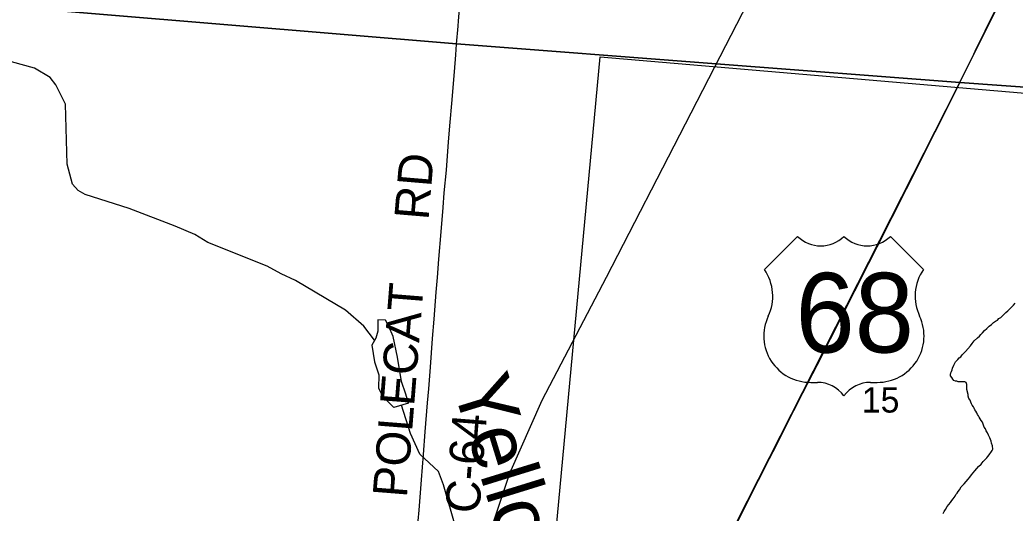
# Model space of a CAD drawing. Extents: x -1.4 to 35.4, y 0 to 22.
# Drawn here: x 19.136 to 20.785, y 18.063 to 18.879 of the extents above; entities that cross this region are included whole.
import ezdxf

# ---------------------------------------------------------------- set-up
doc = ezdxf.new("R2010")
doc.units = 0
for name, color, linetype in [('GM_X_County_Road', 7, 'Continuous'), ('GM_X_County_Road_Text', 7, 'Continuous'), ('GM_X_Minor_Lake', 7, 'Continuous'), ('GM_X_Minor_River', 7, 'Continuous'), ('GM_X_Minor_River_Text', 7, 'Continuous'), ('GM_X_Rail_Line', 7, 'Continuous'), ('GM_X_Section', 7, 'Continuous'), ('GM_X_Section_Text', 7, 'Continuous'), ('GM_X_US_Location', 7, 'Continuous'), ('GM_X_US_Route', 7, 'Continuous'), ('GM_X_US_Shield', 7, 'Continuous'), ('SC_Scratch1', 7, 'Continuous'), ('SH_Cut_Line', 7, 'Continuous')]:
    doc.layers.add(name, color=color, linetype=linetype)

msp = doc.modelspace()

# ---------------------------------------------------------------- linework, layer by layer
at = {"layer": 'GM_X_County_Road'}
for points in [[(19.8597, 18.8392), (19.8621, 18.8687), (19.8628, 18.878), (19.8637, 18.8904), (19.8646, 18.9027), (19.8649, 18.9089), (19.8663, 18.9274), (19.8686, 18.9584), (19.8715, 18.9955), (19.8746, 19.0326), (19.877, 19.0604), (19.8793, 19.0914), (19.8809, 19.1131), (19.8825, 19.1379), (19.884, 19.1782), (19.8852, 19.2247), (19.8856, 19.233)], [(19.8078, 18.1973), (19.8115, 18.2453), (19.8135, 18.2688), (19.8162, 18.3047), (19.8199, 18.3518), (19.8225, 18.384), (19.826, 18.4286), (19.8278, 18.4527), (19.8302, 18.483), (19.8339, 18.5282), (19.8372, 18.569), (19.8393, 18.5932), (19.8427, 18.6303), (19.8463, 18.6773), (19.849, 18.7102), (19.8517, 18.7411), (19.8562, 18.7931), (19.8586, 18.8216), (19.8597, 18.8392)], [(19.7944, 18.0245), (19.7945, 18.0255), (19.7962, 18.0502), (19.7974, 18.0675), (19.8013, 18.1177), (19.805, 18.1598), (19.8078, 18.1973)]]:
    msp.add_lwpolyline(points, dxfattribs=at)
at = {"layer": 'GM_X_Minor_Lake'}
for points in [[(19.78, 18.2446), (19.7757, 18.2598), (19.7686, 18.2809), (19.7618, 18.3209), (19.7545, 18.3552), (19.7473, 18.3716), (19.7418, 18.3824), (19.729, 18.383), (19.7293, 18.364), (19.7261, 18.3527), (19.719, 18.3411), (19.7238, 18.3133), (19.7306, 18.2919), (19.7305, 18.2699), (19.7374, 18.2561), (19.7556, 18.2379)], [(19.78, 18.2446), (19.7556, 18.2379)]]:
    msp.add_lwpolyline(points, dxfattribs=at)
at = {"layer": 'GM_X_Minor_River'}
for points in [[(19.7239, 18.349), (19.706, 18.3725), (19.6755, 18.3989), (19.5929, 18.4481), (19.5689, 18.4592), (19.546, 18.4714), (19.4476, 18.5106), (19.4263, 18.524), (19.3937, 18.5379), (19.3174, 18.5672), (19.2448, 18.5903), (19.2332, 18.597), (19.2236, 18.6075), (19.2148, 18.6403), (19.2118, 18.7397), (19.1962, 18.7719), (19.1866, 18.7839), (19.1604, 18.7996), (19.09, 18.8185), (19.0582, 18.8207), (19.0273, 18.8043), (19.0165, 18.7984), (18.9961, 18.7969), (18.9554, 18.8061)], [(20.6809, 18.303), (20.6829, 18.3075), (20.686, 18.3132), (20.6899, 18.3173), (20.6922, 18.3199), (20.6945, 18.3214), (20.6956, 18.3233), (20.6972, 18.3252), (20.6995, 18.3274), (20.7022, 18.3304), (20.7106, 18.3398), (20.7137, 18.3436), (20.7168, 18.3481), (20.7222, 18.353), (20.7257, 18.356), (20.728, 18.3586), (20.7307, 18.3612), (20.7337, 18.365), (20.738, 18.3687), (20.7414, 18.3721), (20.7453, 18.3751), (20.7487, 18.3785), (20.7522, 18.3807), (20.7552, 18.3825), (20.7575, 18.3848), (20.761, 18.3866), (20.7629, 18.3889), (20.766, 18.3915), (20.7694, 18.3949), (20.7725, 18.3979), (20.7756, 18.4009), (20.779, 18.4043), (20.7821, 18.4073), (20.7848, 18.4103)], [(20.6654, 18.0624), (20.6673, 18.0654), (20.6692, 18.0688), (20.6723, 18.0737), (20.675, 18.0771), (20.6774, 18.0805), (20.6797, 18.0835), (20.682, 18.0865), (20.6835, 18.0888), (20.6851, 18.091), (20.6866, 18.0937), (20.6886, 18.0959), (20.6905, 18.0986), (20.6924, 18.1012), (20.6951, 18.1065), (20.7001, 18.1114), (20.7036, 18.1151), (20.7067, 18.1193), (20.7098, 18.1226), (20.7125, 18.126), (20.7152, 18.1294), (20.7179, 18.1328), (20.721, 18.1366), (20.724, 18.1399), (20.7283, 18.1441), (20.7317, 18.1482), (20.7356, 18.1523), (20.7375, 18.1546), (20.7394, 18.1568), (20.7414, 18.1591), (20.7429, 18.161), (20.7445, 18.1632), (20.7468, 18.1666), (20.7476, 18.1689), (20.7469, 18.1742), (20.7454, 18.1788), (20.7447, 18.1822), (20.7429, 18.1872), (20.7407, 18.1918), (20.7388, 18.1956), (20.7369, 18.1991), (20.7355, 18.2022), (20.7336, 18.2052), (20.7321, 18.2087), (20.7303, 18.2133), (20.7281, 18.2163), (20.7266, 18.219), (20.7251, 18.2217), (20.724, 18.224), (20.7225, 18.2263), (20.721, 18.229), (20.7195, 18.2317), (20.718, 18.234), (20.7165, 18.2363), (20.7154, 18.2386), (20.7132, 18.2417), (20.7125, 18.2436), (20.711, 18.2466), (20.7099, 18.2497), (20.708, 18.2524), (20.7069, 18.2562), (20.7066, 18.2592), (20.7044, 18.2673), (20.7044, 18.2703), (20.7045, 18.2722), (20.7049, 18.2741), (20.7049, 18.276), (20.7034, 18.2791), (20.7015, 18.2799), (20.6993, 18.2803), (20.6966, 18.2803), (20.6939, 18.28), (20.6905, 18.2804), (20.6883, 18.2812), (20.686, 18.2812), (20.6833, 18.2824), (20.6815, 18.2843), (20.6796, 18.2874), (20.6777, 18.2901), (20.6778, 18.2924), (20.6782, 18.295), (20.679, 18.2973), (20.6802, 18.3003), (20.6809, 18.303)], [(19.9061, 17.9463), (19.8885, 17.9531), (19.88, 17.9635), (19.8378, 18.1094), (19.8296, 18.1316), (19.7987, 18.1603), (19.7831, 18.1948), (19.7682, 18.2413)]]:
    msp.add_lwpolyline(points, dxfattribs=at)
at = {"layer": 'GM_X_Rail_Line'}
for points in [[(20.287, 18.8007), (20.5282, 19.269), (20.8153, 19.8201), (20.8331, 19.8546)], [(21.2317, 19.8546), (21.1861, 19.7636), (20.9405, 19.2718), (20.6879, 18.7665)], [(19.8725, 17.517), (19.8633, 17.5865), (19.8576, 17.6579), (19.8569, 17.7477), (19.8664, 17.8471), (19.8899, 17.9549), (19.9213, 18.0493), (19.948, 18.1292), (20.0014, 18.2498), (20.1081, 18.4537), (20.2388, 18.7072), (20.287, 18.8007)], [(20.6879, 18.7665), (20.2308, 17.8662), (20.1919, 17.7967), (20.1657, 17.7644), (20.1271, 17.7246), (20.0692, 17.6745), (19.9621, 17.5898), (19.8725, 17.517)]]:
    msp.add_lwpolyline(points, dxfattribs=at)
at = {"layer": 'GM_X_Section'}
msp.add_lwpolyline([(21.0766, 18.2657), (21.0375, 17.7298), (20.0033, 17.8091), (20.0974, 18.8184), (21.1107, 18.7315), (21.0858, 18.3911)], dxfattribs=at)
at = {"layer": 'GM_X_US_Route'}
for points in [[(20.7138, 18.8178), (20.7187, 18.8278), (20.7351, 18.8613), (20.7494, 18.8907), (20.7568, 18.9059), (20.7634, 18.919)], [(20.6931, 18.7754), (20.701, 18.7914), (20.7138, 18.8178)], [(20.3215, 18.0413), (20.3357, 18.0697), (20.3538, 18.1058), (20.3656, 18.129), (20.378, 18.1534), (20.3899, 18.1766), (20.4054, 18.2077), (20.4181, 18.2326), (20.4332, 18.2618), (20.4497, 18.2938), (20.4638, 18.3215), (20.4789, 18.3514), (20.4971, 18.3874), (20.5189, 18.4306), (20.5424, 18.4765), (20.556, 18.5038), (20.5807, 18.5525), (20.6047, 18.5996), (20.6257, 18.6411), (20.6524, 18.6938), (20.6816, 18.7521), (20.6931, 18.7754)]]:
    msp.add_lwpolyline(points, dxfattribs=at)
at = {"layer": 'GM_X_US_Shield'}
for p, q in [((20.4242, 18.521), (20.3693, 18.466)), ((20.6329, 18.466), (20.578, 18.521)), ((20.4462, 18.2793), (20.4572, 18.2793)), ((20.5451, 18.2793), (20.556, 18.2793))]:
    msp.add_line(p, q, dxfattribs=at)
for centre, radius, start, end in [((20.4627, 18.5602), 0.0549, 225.573, 314.427), ((20.5396, 18.5602), 0.0549, 225.573, 314.427), ((20.3063, 18.4219), 0.0769, 334.5471, 35.0009), ((20.6959, 18.4219), 0.0769, 144.9991, 205.4529), ((20.4453, 18.3562), 0.0769, 154.8319, 270.6383), ((20.5569, 18.3562), 0.0769, 269.3617, 25.1681), ((20.4572, 18.2243), 0.0549, 36.8699, 90), ((20.5451, 18.2243), 0.0549, 90, 143.1301)]:
    msp.add_arc(centre, radius, start, end, dxfattribs=at)
at = {"layer": 'SC_Scratch1'}
for points in [[(18.3046, 18.9691), (19.8595, 18.8397), (20.2896, 18.8065), (20.6929, 18.7759), (21.107, 18.7458), (21.1075, 18.7538), (21.113, 18.819), (21.1175, 18.878), (21.1226, 18.9463)], [(22.2273, 18.6477), (21.107, 18.7458), (20.6929, 18.7759), (20.2896, 18.8065), (19.8595, 18.8397), (18.3046, 18.9691)]]:
    msp.add_lwpolyline(points, dxfattribs=at)
at = {"layer": 'SH_Cut_Line'}
msp.add_lwpolyline([(18.3046, 18.9691), (19.8595, 18.8397), (20.2896, 18.8065), (20.6929, 18.7759), (21.107, 18.7458), (22.2273, 18.6477)], dxfattribs=at)

# ---------------------------------------------------------------- texts
at = {"layer": 'GM_X_County_Road_Text'}
for s, rotation, p in [('RD', 85.1572, (19.813, 18.5469)), ('POLECAT', 85.4618, (19.7772, 18.0875)), ('C-64', 85.5507, (19.8971, 18.061))]:
    msp.add_text(s, height=0.05682, rotation=rotation, dxfattribs=at).set_placement(p)
at = {"layer": 'GM_X_Minor_River_Text'}
msp.add_text('Yellow', height=0.09477, rotation=287.1759, dxfattribs=at).set_placement((19.852, 18.2748))
at = {"layer": 'GM_X_Section_Text'}
msp.add_text('15', height=0.04186, rotation=0, dxfattribs=at).set_placement((20.5307, 18.2293))
at = {"layer": 'GM_X_US_Location'}
for s, p in [('0', (20.501, 18.3936)), ('/', (20.5011, 18.3936))]:
    msp.add_text(s, height=0.000189, dxfattribs=at).set_placement(p)
msp.add_text('68', height=0.000189, rotation=0, dxfattribs=at).set_placement((20.4619, 18.3544))
at = {"layer": 'GM_X_US_Shield'}
msp.add_text('68', height=0.13184, dxfattribs=at).set_placement((20.4209, 18.3287))

doc.saveas('drawing.dxf')
